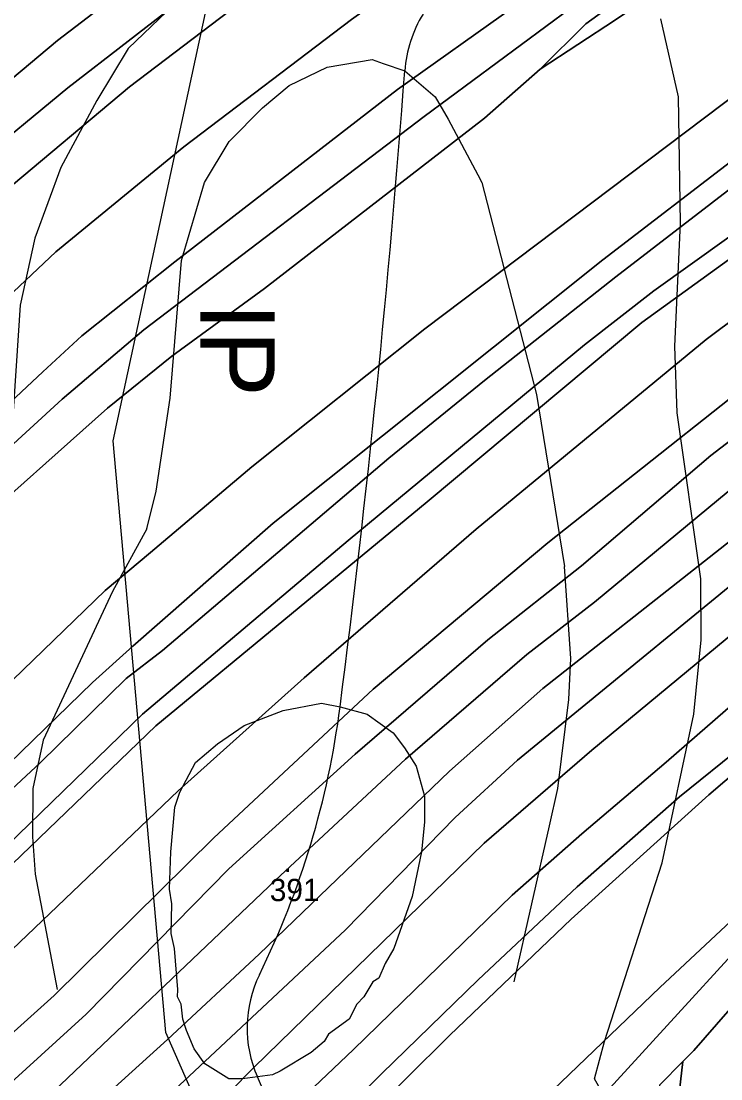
# Model space of a CAD drawing. Extents: x -510989 to -501240, y -1184665 to -1176089.
# Drawn here: x -504263.3 to -504075.2, y -1181588 to -1181303.7 of the extents above; entities that cross this region are included whole.
import ezdxf

# ---------------------------------------------------------------- set-up
doc = ezdxf.new("R2010")
doc.units = 0
for name, color, linetype in [('NAVRH_interakcni_prvky', 7, 'Continuous'), ('orna_puda', 7, 'Continuous'), ('ostatni_plocha_x_ostatni_komunikace', 7, 'Continuous'), ('ostatni_plocha_x_silnice', 7, 'Continuous'), ('STAV_povodi', 7, 'Continuous'), ('STAV_zaplavove_uzemi', 7, 'Continuous'), ('trvaly_travni_porost', 7, 'Continuous'), ('vrstevnice_01', 7, 'Continuous'), ('vrstevnice_02', 7, 'Continuous'), ('vrstevnice_03', 7, 'Continuous'), ('vrstevnice_05', 7, 'Continuous')]:
    doc.layers.add(name, color=color, linetype=linetype)

msp = doc.modelspace()

# ---------------------------------------------------------------- linework, layer by layer
at = {"layer": 'NAVRH_interakcni_prvky'}
msp.add_lwpolyline([(-504180.72, -1181675.18), (-504224.4, -1181575.54), (-504238.64, -1181416.52), (-504212.53, -1181295.47), (-504146.08, -1181212.4), (-504053.51, -1181124.58)], dxfattribs=at)
at = {"layer": 'orna_puda'}
for points in [[(-504031.44, -1181177.54), (-504022.27, -1181171.19), (-504013.39, -1181189.25), (-504019.18, -1181193.67), (-504113.03, -1181259.49), (-504174.49, -1181303.18), (-504219.59, -1181337.41), (-504254.01, -1181365.71), (-504302.81, -1181411.72), (-504341.52, -1181445.92), (-504341.04, -1181430.83), (-504339.73, -1181414.78), (-504315.62, -1181394.24), (-504268.13, -1181349.85), (-504234.24, -1181321.28), (-504197.74, -1181293.56), (-504131.16, -1181248.3), (-504085.57, -1181217), (-504053.73, -1181194.36)], [(-504013.39, -1181189.25), (-504009.07, -1181198.04), (-504003.79, -1181208.76), (-504101.1, -1181277.93), (-504130.86, -1181299.83), (-504162.16, -1181322.06), (-504221.98, -1181368.35), (-504247, -1181388.24), (-504257.49, -1181397.92), (-504319.7, -1181456.2), (-504339.08, -1181472.56), (-504339.62, -1181464.15), (-504340.18, -1181458.94), (-504341.22, -1181451.64), (-504341.52, -1181445.92), (-504302.81, -1181411.72), (-504254.01, -1181365.71), (-504219.59, -1181337.41), (-504174.49, -1181303.18), (-504113.03, -1181259.49), (-504019.18, -1181193.67)], [(-503999.84, -1181216.8), (-504028.31, -1181238.29), (-504076.03, -1181269.68), (-504109.23, -1181295.35), (-504154.96, -1181329.28), (-504230.37, -1181386.63), (-504252.32, -1181405.26), (-504285.04, -1181435.21), (-504337.25, -1181485.24), (-504358.78, -1181506.18), (-504354.61, -1181498.79), (-504350.74, -1181493.55), (-504338.84, -1181481.02), (-504339.08, -1181472.56), (-504319.7, -1181456.2), (-504257.49, -1181397.92), (-504247, -1181388.24), (-504221.98, -1181368.35), (-504162.16, -1181322.06), (-504130.86, -1181299.83), (-504101.1, -1181277.93), (-504003.79, -1181208.76)], [(-503980.02, -1181257.1), (-503973.89, -1181269.55), (-503977.1, -1181271.98), (-504027.29, -1181308.5), (-504070.29, -1181339.68), (-504107.01, -1181367.8), (-504195.59, -1181438.64), (-504233.31, -1181471.69), (-504244.12, -1181481.44), (-504269.99, -1181506.44), (-504326.71, -1181559.76), (-504359.98, -1181587.77), (-504377.18, -1181600.3), (-504382.53, -1181588.34), (-504381.74, -1181584.82), (-504346.14, -1181557.1), (-504301.7, -1181515.58), (-504240.75, -1181456.77), (-504228.53, -1181446.55), (-504201.3, -1181423.46), (-504154.79, -1181386.39), (-504064.64, -1181318.38), (-504034.48, -1181296.36), (-503994.09, -1181267.31)], [(-504055.85, -1181268.05), (-504066.9, -1181279.77), (-504077.15, -1181285.39), (-504103.53, -1181303.33), (-504123.81, -1181316.55), (-504111.54, -1181304.4), (-504070, -1181274.25)], [(-503944.07, -1181330.17), (-503962.31, -1181344.77), (-504064.91, -1181423.18), (-504109.25, -1181459.83), (-504127.4, -1181473.98), (-504160.04, -1181502.09), (-504194.96, -1181534.62), (-504260.14, -1181596.6), (-504303.09, -1181634.43), (-504336.37, -1181660.22), (-504347.05, -1181667.61), (-504350.91, -1181658.99), (-504315.13, -1181632.29), (-504290.31, -1181611.06), (-504245.87, -1181570.69), (-504207.48, -1181531.56), (-504173.54, -1181500.72), (-504137.91, -1181470.01), (-504112.69, -1181450.12), (-504077.92, -1181420.42), (-504049.09, -1181398.26), (-503995.76, -1181359.87), (-503976.68, -1181345.32), (-503948.03, -1181322.12)], [(-503942.1, -1181334.17), (-503939.89, -1181338.66), (-503941.64, -1181340.1), (-504036.16, -1181414.61), (-504123.08, -1181483.11), (-504148.17, -1181505.32), (-504199.33, -1181554.54), (-504223.99, -1181577.43), (-504255.31, -1181605.86), (-504302.39, -1181646.52), (-504333.53, -1181670.75), (-504342.67, -1181677.41), (-504344.68, -1181672.91), (-504347.05, -1181667.61), (-504336.37, -1181660.22), (-504303.09, -1181634.43), (-504260.14, -1181596.6), (-504194.96, -1181534.62), (-504160.04, -1181502.09), (-504127.4, -1181473.98), (-504109.25, -1181459.83), (-504064.91, -1181423.18), (-503962.31, -1181344.77), (-503944.07, -1181330.17)], [(-503939.89, -1181338.66), (-503936.34, -1181345.88), (-503944.63, -1181352.64), (-504023.33, -1181415.35), (-504054.92, -1181440.88), (-504129.87, -1181502.39), (-504146.7, -1181517.74), (-504176.13, -1181548), (-504219.49, -1181588.54), (-504245.7, -1181612.57), (-504295.39, -1181654.87), (-504302.39, -1181646.52), (-504255.31, -1181605.86), (-504223.99, -1181577.43), (-504199.33, -1181554.54), (-504148.17, -1181505.32), (-504123.08, -1181483.11), (-504036.16, -1181414.61), (-503941.64, -1181340.1)], [(-504036.26, -1181341.11), (-504026.59, -1181350.42), (-504051.54, -1181368.52), (-504079.21, -1181389.26), (-504140.99, -1181440.26), (-504187.21, -1181480.2), (-504221.1, -1181510.64), (-504278.03, -1181564.9), (-504311.79, -1181596), (-504328.96, -1181609.46), (-504361.76, -1181634.74), (-504368.28, -1181620.18), (-504359.83, -1181614.36), (-504325.51, -1181586.47), (-504304.33, -1181567.44), (-504227.12, -1181493.15), (-504154.15, -1181432.9), (-504096.44, -1181384.65)], [(-503944.63, -1181352.64), (-503936.34, -1181345.88), (-503932.23, -1181354.23), (-503999.82, -1181408.51), (-504109.96, -1181499.71), (-504138.91, -1181524.63), (-504200.79, -1181585.03), (-504220.42, -1181604.9), (-504255.3, -1181636.01), (-504286.11, -1181662.28), (-504318.39, -1181686.88), (-504333.77, -1181697.3), (-504338.44, -1181686.86), (-504295.39, -1181654.87), (-504245.7, -1181612.57), (-504219.49, -1181588.54), (-504176.13, -1181548), (-504146.7, -1181517.74), (-504129.87, -1181502.39), (-504054.92, -1181440.88), (-504023.33, -1181415.35)], [(-504038.49, -1181477.53), (-504020.49, -1181493.63), (-504052.11, -1181526.57), (-504091.63, -1181563.5), (-504124.83, -1181595.32), (-504137.42, -1181607.75), (-504155.8, -1181627.38), (-504185.42, -1181656.07), (-504209.06, -1181675), (-504251.71, -1181707.68), (-504309.83, -1181750.79), (-504321.41, -1181724.92), (-504299.88, -1181709.69), (-504279.32, -1181694.3), (-504250.04, -1181669.72), (-504222.74, -1181646.59), (-504206.72, -1181632.65), (-504177.73, -1181605.67), (-504162.53, -1181590.62), (-504159.86, -1181587.97), (-504148.12, -1181576.34), (-504115.44, -1181545.08), (-504078.43, -1181511.72)]]:
    msp.add_lwpolyline(points, close=True, dxfattribs=at)
for points in [[(-504068, -1181191.56), (-504202.11, -1181283.84), (-504250.78, -1181321.58), (-504276.27, -1181342.54), (-504339.91, -1181402.27), (-504339.73, -1181414.78), (-504341.04, -1181430.83), (-504341.52, -1181445.92), (-504341.22, -1181451.64), (-504340.18, -1181458.94), (-504339.62, -1181464.15), (-504339.08, -1181472.56), (-504338.84, -1181481.02), (-504350.74, -1181493.55), (-504354.61, -1181498.79), (-504358.78, -1181506.18), (-504366.1, -1181523.91), (-504368.35, -1181529.62), (-504372.78, -1181543.85), (-504377.58, -1181561.2)], [(-504064.64, -1181318.38), (-504154.79, -1181386.39), (-504201.3, -1181423.46), (-504228.53, -1181446.55), (-504240.75, -1181456.77), (-504301.7, -1181515.58), (-504346.14, -1181557.1), (-504381.74, -1181584.82), (-504378.88, -1181565.81), (-504377.58, -1181561.2), (-504372.78, -1181543.85), (-504368.35, -1181529.62), (-504366.1, -1181523.91), (-504354.41, -1181514.74), (-504310.8, -1181472.01), (-504279.2, -1181442.52), (-504240.11, -1181407.72), (-504222.79, -1181393.73), (-504197.92, -1181375.52), (-504138.78, -1181329.71), (-504123.81, -1181316.55), (-504103.53, -1181303.33), (-504077.15, -1181285.39), (-504066.9, -1181279.77)], [(-504321.64, -1181299.38), (-504325.21, -1181317.93), (-504328.12, -1181333.6), (-504330.15, -1181342.44), (-504331.1, -1181348.99), (-504333.72, -1181367.04), (-504336.16, -1181384.18), (-504285.45, -1181335.54), (-504253.54, -1181308.83), (-504216.71, -1181280.6)], [(-504337.64, -1181590.56), (-504315.67, -1181571.6), (-504288.62, -1181546.13), (-504230.73, -1181489.99), (-504175.46, -1181443.32), (-504111.85, -1181390.71), (-504093.27, -1181376.13), (-504073.12, -1181361.78), (-504017.65, -1181321.72), (-504003.54, -1181312.07), (-503966.55, -1181284.47), (-503964.3, -1181289.04), (-503966.71, -1181290.92), (-503988.68, -1181306.68), (-504008.98, -1181321.88), (-504036.26, -1181341.11), (-504096.44, -1181384.65), (-504154.15, -1181432.9), (-504227.12, -1181493.15), (-504304.33, -1181567.44), (-504325.51, -1181586.47), (-504359.83, -1181614.36)], [(-504311.79, -1181596), (-504278.03, -1181564.9), (-504221.1, -1181510.64), (-504187.21, -1181480.2), (-504140.99, -1181440.26), (-504079.21, -1181389.26), (-504051.54, -1181368.52), (-504026.59, -1181350.42), (-503992.91, -1181326.67), (-503967.94, -1181308.83), (-503958.25, -1181301.35), (-503952.48, -1181313.07), (-503971.62, -1181326.86), (-504047.1, -1181384.76), (-504121.78, -1181443.96), (-504168.7, -1181483.28), (-504211.54, -1181523.2), (-504254.5, -1181565.62), (-504289.52, -1181597.05)], [(-504289.52, -1181597.05), (-504254.5, -1181565.62), (-504211.54, -1181523.2), (-504168.7, -1181483.28), (-504121.78, -1181443.96), (-504047.1, -1181384.76), (-503971.62, -1181326.86), (-503952.48, -1181313.07), (-503948.03, -1181322.12), (-503976.68, -1181345.32), (-503995.76, -1181359.87), (-504049.09, -1181398.26), (-504077.92, -1181420.42), (-504112.69, -1181450.12), (-504137.91, -1181470.01), (-504173.54, -1181500.72), (-504207.48, -1181531.56), (-504245.87, -1181570.69), (-504290.31, -1181611.06)], [(-504367.79, -1181601.05), (-504323.53, -1181564.59), (-504298.04, -1181540.63), (-504286.63, -1181529.44), (-504258.17, -1181502.98), (-504235.12, -1181480.4), (-504225.38, -1181472.86), (-504164.5, -1181421.18), (-504138.76, -1181400.31), (-504103.51, -1181372.38), (-504068.78, -1181345.73)], [(-504220.42, -1181604.9), (-504200.79, -1181585.03), (-504138.91, -1181524.63), (-504109.96, -1181499.71), (-503999.82, -1181408.51), (-503932.23, -1181354.23), (-503929.93, -1181358.91), (-503944.36, -1181373.1), (-503961.19, -1181387.11), (-503994.8, -1181414.13), (-503991.53, -1181414.41), (-504016.81, -1181438.88), (-504030.95, -1181451.5), (-504089.97, -1181502.91), (-504112.64, -1181522.2), (-504131.34, -1181538.65), (-504173.95, -1181580.18), (-504188.24, -1181593.72)], [(-504124.83, -1181595.32), (-504091.63, -1181563.5), (-504052.11, -1181526.57), (-504020.49, -1181493.63), (-504038.49, -1181477.53), (-504011.44, -1181453.58), (-503993.81, -1181435.36), (-503989.03, -1181430.17), (-503978.39, -1181416.77), (-503981.49, -1181415.42), (-503984.85, -1181414.14), (-503991.53, -1181414.41), (-503994.8, -1181414.13), (-503961.19, -1181387.11), (-503944.36, -1181373.1), (-503929.93, -1181358.91), (-503925.74, -1181367.43), (-503935.1, -1181377.41), (-503990.42, -1181464.68), (-504018.64, -1181495.97), (-504140.54, -1181629.34)], [(-504073.12, -1181361.78), (-504093.27, -1181376.13), (-504111.85, -1181390.71), (-504175.46, -1181443.32), (-504230.73, -1181489.99), (-504288.62, -1181546.13), (-504315.67, -1181571.6), (-504337.64, -1181590.56)], [(-504188.24, -1181593.72), (-504173.95, -1181580.18), (-504131.34, -1181538.65), (-504112.64, -1181522.2), (-504089.97, -1181502.91), (-504030.95, -1181451.5), (-504016.81, -1181438.88), (-503991.53, -1181414.41), (-503984.85, -1181414.14), (-503981.49, -1181415.42), (-504017.23, -1181451.51), (-504038.56, -1181469.74), (-504069.23, -1181498.4), (-504086.37, -1181512.24), (-504113.88, -1181536.39), (-504140.47, -1181561.44), (-504166.38, -1181586.63), (-504167.15, -1181587.38), (-504172.49, -1181592.58)], [(-504172.49, -1181592.58), (-504167.15, -1181587.38), (-504166.38, -1181586.63), (-504140.47, -1181561.44), (-504113.88, -1181536.39), (-504086.37, -1181512.24), (-504069.23, -1181498.4), (-504038.56, -1181469.74), (-504017.23, -1181451.51), (-503981.49, -1181415.42), (-503978.39, -1181416.77), (-503989.03, -1181430.17), (-503993.81, -1181435.36), (-504011.44, -1181453.58), (-504038.49, -1181477.53), (-504078.43, -1181511.72), (-504115.44, -1181545.08), (-504148.12, -1181576.34), (-504159.86, -1181587.97), (-504162.53, -1181590.62)]]:
    msp.add_lwpolyline(points, dxfattribs=at)
at = {"layer": 'ostatni_plocha_x_ostatni_komunikace'}
msp.add_lwpolyline([(-504091.66, -1181589.66), (-504085.43, -1181583.39), (-504089.14, -1181615.28), (-504091.39, -1181633.16), (-504092.48, -1181659.16), (-504093.11, -1181669.4), (-504095.23, -1181665.11), (-504095.44, -1181645.57), (-504095.37, -1181633.27), (-504092.72, -1181610.11)], close=True, dxfattribs=at)
at = {"layer": 'ostatni_plocha_x_silnice'}
for points in [[(-504140.54, -1181629.34), (-504018.64, -1181495.97)], [(-504057.5, -1181551.71), (-504082.51, -1181580.45), (-504085.43, -1181583.39), (-504091.66, -1181589.66)]]:
    msp.add_lwpolyline(points, dxfattribs=at)
at = {"layer": 'STAV_povodi'}
for centre, radius, start, end in [((-504125.94, -1181319.57), 34.35, 148.7413, 175.7168), ((-507374.38, -1181076.27), 3223.19, 352.66102, 355.7168), ((-504405.67, -1181458.63), 229.96, 333.8243, 352.661), ((-504170.26, -1181574.34), 32.35, 153.8243, 204.0059), ((-505195.78, -1182031.05), 1090.27, 17.13056, 24.00586)]:
    msp.add_arc(centre, radius, start, end, dxfattribs=at)
at = {"layer": 'STAV_zaplavove_uzemi'}
for points in [[(-504594.17, -1181642.09), (-504629.77, -1181535.28), (-504650.39, -1181443.46), (-504674.75, -1181355.39), (-504706.6, -1181265.44), (-504719.72, -1181182.99), (-504747.83, -1181113.66), (-504727.29, -1181064.42), (-504683.65, -1181020.77), (-504624.52, -1180967.28), (-504575.24, -1180927.85), (-504544.27, -1180915.18), (-504445.72, -1180881.39), (-504404.89, -1180867.31), (-504292.26, -1180829.3), (-504179.63, -1180791.29), (-504099.38, -1180734.98), (-504020.54, -1180698.37), (-503957.18, -1180675.84), (-503893.83, -1180664.58), (-503865.67, -1180678.66), (-503817.8, -1180689.92), (-503788.24, -1180689.92), (-503764.3, -1180695.55), (-503736.15, -1180687.11), (-503717.85, -1180698.37), (-503716.44, -1180708.23)], [(-502250.32, -1184002.61), (-502355.07, -1183875.41), (-502442.37, -1183790.61), (-502477.29, -1183700.82), (-502532.16, -1183578.61), (-502567.08, -1183448.91), (-502626.05, -1183402.34), (-502705.41, -1183380.59), (-502814.2, -1183349.87), (-502882.03, -1183297.39), (-502931.95, -1183237.24), (-503042.02, -1183107.97), (-503139.64, -1183018.94), (-503222.14, -1182957.59), (-503308.56, -1182839.96), (-503316.24, -1182784.92), (-503330.32, -1182756.77), (-503348.24, -1182719.65), (-503334.16, -1182651.82), (-503323.92, -1182595.5), (-503313.68, -1182526.39), (-503294.1, -1182480.5), (-503251.86, -1182396.03), (-503229.34, -1182314.37), (-503216.1, -1182227.15), (-503242.43, -1182174.5), (-503271.86, -1182129.59), (-503287.34, -1182081.58), (-503343.88, -1182028.1), (-503361.79, -1182008.91), (-503396.35, -1181952.59), (-503442.43, -1181933.39), (-503497.46, -1181888.6), (-503525.62, -1181860.44), (-503528.18, -1181837.4), (-503548.66, -1181767.01), (-503558.9, -1181729.89), (-503576.82, -1181682.53), (-503578.1, -1181621.1), (-503567.86, -1181572.46), (-503552.5, -1181536.63), (-503538.04, -1181458.36), (-503518.33, -1181411.9), (-503509.88, -1181341.51), (-503497.21, -1181207.63), (-503499.77, -1181097.56), (-503498.02, -1181031.35), (-503510.82, -1180970.85), (-503549.22, -1180952.23), (-503571.32, -1180940.6), (-503605.07, -1180937.11), (-503651.61, -1180939.44), (-503671.39, -1180917.33), (-503679.53, -1180892.89), (-503713.27, -1180871.95), (-503727.24, -1180859.15), (-503734.22, -1180833.55), (-503728.4, -1180799.81), (-503741.2, -1180770.72), (-503722.82, -1180725.17), (-503721.54, -1180703.41), (-503731.78, -1180697.01), (-503767.61, -1180699.57), (-503790.65, -1180697.01), (-503817.53, -1180697.01), (-503861.04, -1180686.77), (-503889.2, -1180675.25), (-503900.72, -1180668.85), (-503953.2, -1180679.09), (-503997.99, -1180697.01), (-504063.27, -1180722.61), (-504109.34, -1180749.49), (-504142.62, -1180776.36), (-504177.18, -1180796.84), (-504211.73, -1180817.32), (-504414.98, -1180961.5), (-504472.7, -1180998.11), (-504544.51, -1181068.5), (-504600.82, -1181143.12), (-504621.94, -1181196.62), (-504641.65, -1181267.01), (-504660.25, -1181350.62), (-504634.7, -1181398.32), (-504617.66, -1181447.72), (-504600.62, -1181492.01), (-504587, -1181548.23), (-504592.11, -1181628.29), (-504569.96, -1181682.81), (-504568.26, -1181664.07), (-504554.63, -1181621.48), (-504547.82, -1181597.63)]]:
    msp.add_spline(points, degree=3, dxfattribs=at)
at = {"layer": 'trvaly_travni_porost'}
for points in [[(-504040.42, -1181134.3), (-504036.01, -1181143.25), (-504031.19, -1181153.05), (-504064.76, -1181176.34), (-504118.81, -1181213.6), (-504195.36, -1181266.3), (-504216.71, -1181280.6), (-504253.54, -1181308.83), (-504285.45, -1181335.54), (-504336.16, -1181384.18), (-504333.72, -1181367.04), (-504331.1, -1181348.99), (-504330.15, -1181342.44), (-504328.12, -1181333.6), (-504299.96, -1181306.14), (-504254.48, -1181269.63), (-504184.5, -1181220.35), (-504125.67, -1181180.76), (-504080.12, -1181149.25), (-504045.34, -1181124.29)], [(-504022.27, -1181171.19), (-504031.44, -1181177.54), (-504053.73, -1181194.36), (-504085.57, -1181217), (-504131.16, -1181248.3), (-504197.74, -1181293.56), (-504234.24, -1181321.28), (-504268.13, -1181349.85), (-504315.62, -1181394.24), (-504339.73, -1181414.78), (-504339.91, -1181402.27), (-504276.27, -1181342.54), (-504250.78, -1181321.58), (-504202.11, -1181283.84), (-504068, -1181191.56), (-504026.74, -1181162.09)]]:
    msp.add_lwpolyline(points, close=True, dxfattribs=at)
for points in [[(-504070, -1181274.25), (-504111.54, -1181304.4), (-504123.81, -1181316.55), (-504138.78, -1181329.71), (-504197.92, -1181375.52), (-504222.79, -1181393.73), (-504240.11, -1181407.72), (-504279.2, -1181442.52), (-504310.8, -1181472.01), (-504354.41, -1181514.74), (-504366.1, -1181523.91), (-504358.78, -1181506.18), (-504337.25, -1181485.24), (-504285.04, -1181435.21), (-504252.32, -1181405.26), (-504230.37, -1181386.63), (-504154.96, -1181329.28), (-504109.23, -1181295.35), (-504076.03, -1181269.68), (-504028.31, -1181238.29)], [(-504377.18, -1181600.3), (-504359.98, -1181587.77), (-504326.71, -1181559.76), (-504269.99, -1181506.44), (-504244.12, -1181481.44), (-504233.31, -1181471.69), (-504195.59, -1181438.64), (-504107.01, -1181367.8), (-504070.29, -1181339.68)], [(-504068.78, -1181345.73), (-504103.51, -1181372.38), (-504138.76, -1181400.31), (-504164.5, -1181421.18), (-504225.38, -1181472.86), (-504235.12, -1181480.4), (-504258.17, -1181502.98), (-504286.63, -1181529.44), (-504298.04, -1181540.63), (-504323.53, -1181564.59), (-504367.79, -1181601.05)], [(-504089.14, -1181615.28), (-504085.43, -1181583.39), (-504082.51, -1181580.45), (-504057.5, -1181551.71)]]:
    msp.add_lwpolyline(points, dxfattribs=at)
at = {"layer": 'vrstevnice_01'}
msp.add_lwpolyline([(-504163.31, -1181495), (-504160.31, -1181499), (-504157.19, -1181504), (-504154.91, -1181512), (-504154.91, -1181519), (-504155.69, -1181527), (-504158.19, -1181539), (-504163.19, -1181553), (-504165.5, -1181557), (-504167.19, -1181561), (-504168.81, -1181562), (-504171.19, -1181566), (-504173.09, -1181568), (-504175.19, -1181572), (-504180.69, -1181576), (-504181.91, -1181578), (-504185.41, -1181581), (-504193.69, -1181586), (-504195.81, -1181587), (-504203.81, -1181588), (-504207.5, -1181588), (-504214, -1181584), (-504216.81, -1181580), (-504218.91, -1181575), (-504219.91, -1181572), (-504220.31, -1181568), (-504221.31, -1181566), (-504221.19, -1181564), (-504222.09, -1181553), (-504223, -1181549), (-504222.81, -1181541), (-504223.41, -1181537), (-504223.09, -1181527), (-504222, -1181515), (-504220.69, -1181511), (-504216.5, -1181503), (-504210.59, -1181498), (-504203.41, -1181493), (-504192.91, -1181489), (-504182.59, -1181487), (-504177.59, -1181488), (-504170.31, -1181490), (-504163.31, -1181495)], dxfattribs=at)
at = {"layer": 'vrstevnice_02'}
for points in [[(-504220.09, -1181297), (-504234.59, -1181311), (-504243, -1181325), (-504252.69, -1181343), (-504259.69, -1181362), (-504263.59, -1181380), (-504265.81, -1181414), (-504267.91, -1181431), (-504269.83, -1181436.52)], [(-504080.65, -1181453.59), (-504087, -1181409), (-504087.59, -1181391), (-504086.09, -1181358), (-504086.59, -1181324), (-504091.41, -1181303)], [(-504107, -1181592), (-504109.19, -1181588), (-504106.5, -1181578), (-504091, -1181530), (-504082.5, -1181490), (-504080.5, -1181470), (-504080.65, -1181453.59)]]:
    msp.add_lwpolyline(points, dxfattribs=at)
at = {"layer": 'vrstevnice_03'}
for points in [[(-504229.58, -1181440.15), (-504227, -1181430), (-504223.31, -1181405), (-504220.19, -1181368), (-504214.09, -1181347), (-504207.41, -1181336), (-504198.41, -1181327), (-504191.31, -1181321), (-504181.09, -1181316), (-504169, -1181314), (-504166, -1181315), (-504160.19, -1181317), (-504152, -1181324), (-504148.5, -1181330), (-504140.59, -1181345), (-504139.5, -1181347), (-504124.81, -1181404), (-504117.23, -1181450.29)], [(-504229.58, -1181440.15), (-504238.81, -1181457), (-504257.41, -1181497), (-504260.19, -1181510), (-504260.31, -1181523), (-504259.59, -1181533), (-504253.69, -1181564)], [(-504130.81, -1181562), (-504121.31, -1181520), (-504119.09, -1181510), (-504116.09, -1181486), (-504115.59, -1181475), (-504117.23, -1181450.29)]]:
    msp.add_lwpolyline(points, dxfattribs=at)

# ---------------------------------------------------------------- texts
at = {"layer": 'NAVRH_interakcni_prvky'}
msp.add_text('IP', height=20, rotation=270, dxfattribs=at).set_placement((-504215.18, -1181379.36))
at = {"layer": 'vrstevnice_05'}
for s, p in [('.', (-504192.82, -1181532.46)), ('391', (-504196.5, -1181540.26))]:
    msp.add_text(s, height=6, dxfattribs=at).set_placement(p)

doc.saveas('drawing.dxf')
